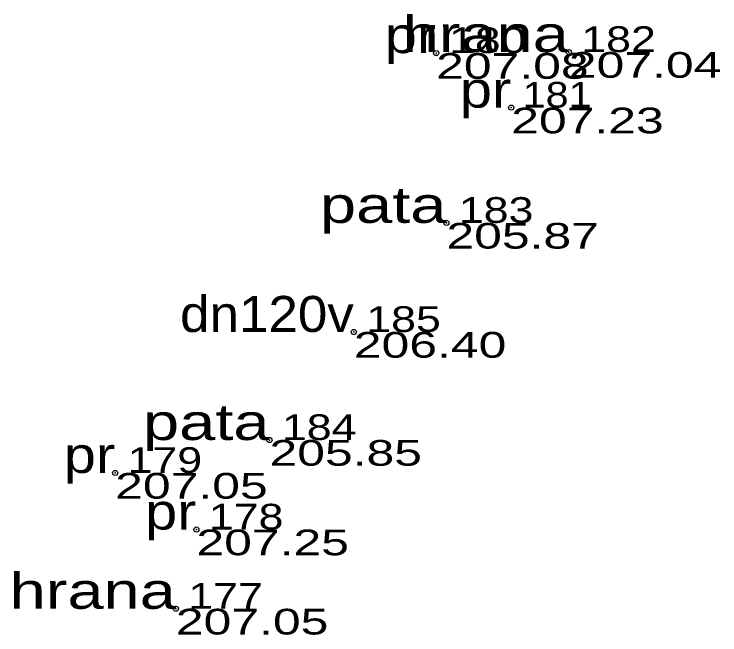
# Model space of a CAD drawing. Extents: x -535846 to -533631, y -1143344 to -1142802.
# Drawn here: x -534035.16 to -534028.3, y -1143095.22 to -1143089.19 of the extents above; entities that cross this region are included whole.
import ezdxf
from ezdxf.enums import TextEntityAlignment as Align

# ---------------------------------------------------------------- set-up
doc = ezdxf.new("R2010")
doc.units = 0
doc.header["$LTSCALE"] = 0.1
doc.header["$PDMODE"] = 32
doc.header["$PDSIZE"] = 0.05
for name, color, linetype in [('1', 7, 'Continuous'), ('18', 7, 'Continuous'), ('2', 7, 'Continuous'), ('3', 7, 'Continuous')]:
    doc.layers.add(name, color=color, linetype=linetype)

msp = doc.modelspace()

# ---------------------------------------------------------------- linework, layer by layer
at = {"layer": '1'}
for p in [(-534031.06, -1143089.57), (-534029.77, -1143089.56), (-534030.33, -1143090.1), (-534030.96, -1143091.22), (-534031.86, -1143092.28), (-534032.68, -1143093.33), (-534034.18, -1143093.65), (-534033.39, -1143094.2), (-534033.59, -1143094.97)]:
    msp.add_point(p, dxfattribs=at)

# ---------------------------------------------------------------- texts
at = {"layer": '18'}
for s, width, p in [('hrana', 1.35, (-534029.77, -1143089.56)), ('pr', 1.2, (-534031.06, -1143089.57)), ('pr', 1.2, (-534030.33, -1143090.1)), ('pata', 1.35, (-534030.96, -1143091.22)), ('dn120v', 1.1, (-534031.86, -1143092.28)), ('pata', 1.35, (-534032.68, -1143093.33)), ('pr', 1.2, (-534034.18, -1143093.65)), ('pr', 1.2, (-534033.39, -1143094.2)), ('hrana', 1.35, (-534033.59, -1143094.97))]:
    msp.add_text(s, height=0.35, dxfattribs=dict(at, width=width)).set_placement(p, align=Align.RIGHT)
at = {"layer": '2'}
for s, width, p in [(' 180', 1.35, (-534031.06, -1143089.57)), (' 182', 1.3, (-534029.77, -1143089.56)), (' 181', 1.2, (-534030.33, -1143090.1)), (' 183', 1.3, (-534030.96, -1143091.22)), (' 185', 1.3, (-534031.86, -1143092.28)), (' 184', 1.3, (-534032.68, -1143093.33)), (' 179', 1.3, (-534034.18, -1143093.65)), (' 178', 1.3, (-534033.39, -1143094.2)), (' 177', 1.3, (-534033.59, -1143094.97))]:
    msp.add_text(s, height=0.25, dxfattribs=dict(at, width=width)).set_placement(p)
at = {"layer": '3', "width": 1.45}
for s, p in [('207.08 ', (-534031.06, -1143089.82)), ('207.04 ', (-534029.77, -1143089.81)), ('207.23 ', (-534030.33, -1143090.35)), ('205.87 ', (-534030.96, -1143091.47)), ('206.40 ', (-534031.86, -1143092.53)), ('205.85 ', (-534032.68, -1143093.58)), ('207.05 ', (-534034.18, -1143093.9)), ('207.25 ', (-534033.39, -1143094.45)), ('207.05 ', (-534033.59, -1143095.22))]:
    msp.add_text(s, height=0.25, dxfattribs=at).set_placement(p)

doc.saveas('drawing.dxf')
